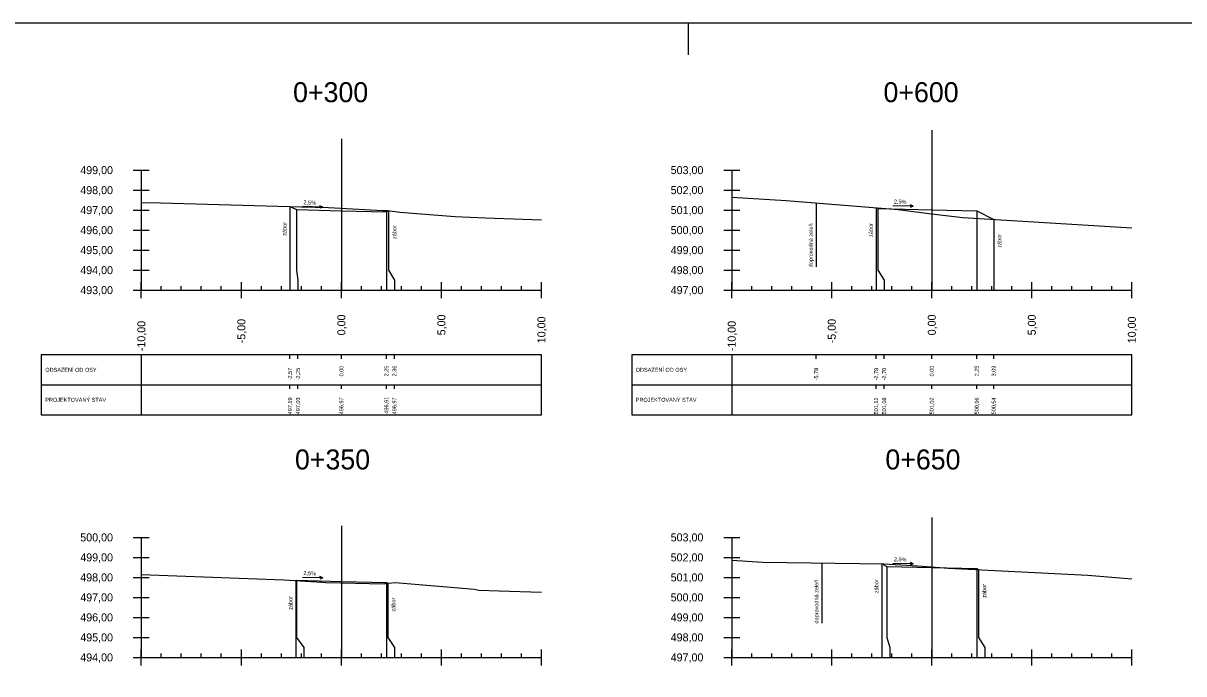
# Model space of a CAD drawing. Extents: x -631407 to -631215, y -1089700 to -1088598.
# Drawn here: x -631374.6 to -631316.6, y -1089327.7 to -1089295.2 of the extents above; entities that cross this region are included whole.
import ezdxf

# ---------------------------------------------------------------- set-up
doc = ezdxf.new("R2010")
doc.units = 0
for name, color, linetype in [('08_LEGENDA_HV', 7, 'Continuous'), ('59', 7, 'Continuous'), ('DTM-Breaklines', 7, 'Continuous'), ('NIVELETA_VYSKY', 7, 'Continuous'), ('REZ_BODY', 7, 'Continuous'), ('REZ_ODSTUPY', 7, 'Continuous'), ('REZ_POPIS', 7, 'Continuous'), ('REZ_RAMY', 7, 'Continuous'), ('REZ_STANICENI', 7, 'Continuous'), ('REZ_SVISLE', 7, 'Continuous'), ('REZ_TENKA', 7, 'Continuous'), ('REZ_TLUSTA', 7, 'Continuous'), ('TABULKA_POPIS', 7, 'Continuous'), ('TEREN', 7, 'Continuous'), ('zábor', 7, 'Continuous')]:
    doc.layers.add(name, color=color, linetype=linetype)

msp = doc.modelspace()

# ---------------------------------------------------------------- linework, layer by layer
at = {"layer": '08_LEGENDA_HV'}
msp.add_lwpolyline([(-631215.384, -1089413.965), (-631215.384, -1089295.165), (-631407.014, -1089295.165), (-631407.014, -1089413.965)], close=True, dxfattribs=at)
at = {"layer": '59'}
for p, q in [((-631369.144, -1089302.511), (-631368.344, -1089302.511)), ((-631368.744, -1089302.511), (-631368.744, -1089308.511)), ((-631339.63, -1089302.511), (-631338.83, -1089302.511)), ((-631339.23, -1089302.511), (-631339.23, -1089308.511)), ((-631369.144, -1089303.511), (-631368.344, -1089303.511)), ((-631339.63, -1089303.511), (-631338.83, -1089303.511)), ((-631369.144, -1089304.511), (-631368.344, -1089304.511)), ((-631339.63, -1089304.511), (-631338.83, -1089304.511)), ((-631369.144, -1089305.511), (-631368.344, -1089305.511)), ((-631339.63, -1089305.511), (-631338.83, -1089305.511)), ((-631369.144, -1089306.511), (-631368.344, -1089306.511)), ((-631339.63, -1089306.511), (-631338.83, -1089306.511)), ((-631369.144, -1089307.511), (-631368.344, -1089307.511)), ((-631339.63, -1089307.511), (-631338.83, -1089307.511)), ((-631369.144, -1089308.511), (-631368.344, -1089308.511)), ((-631339.63, -1089308.511), (-631338.83, -1089308.511)), ((-631369.144, -1089320.873), (-631368.344, -1089320.873)), ((-631368.744, -1089320.873), (-631368.744, -1089326.873)), ((-631339.63, -1089320.873), (-631338.83, -1089320.873)), ((-631339.23, -1089320.873), (-631339.23, -1089326.873)), ((-631369.144, -1089321.873), (-631368.344, -1089321.873)), ((-631339.63, -1089321.873), (-631338.83, -1089321.873)), ((-631369.144, -1089322.873), (-631368.344, -1089322.873)), ((-631339.63, -1089322.873), (-631338.83, -1089322.873)), ((-631369.144, -1089323.873), (-631368.344, -1089323.873)), ((-631339.63, -1089323.873), (-631338.83, -1089323.873)), ((-631369.144, -1089324.873), (-631368.344, -1089324.873)), ((-631339.63, -1089324.873), (-631338.83, -1089324.873)), ((-631369.144, -1089325.873), (-631368.344, -1089325.873)), ((-631339.63, -1089325.873), (-631338.83, -1089325.873)), ((-631369.144, -1089326.873), (-631368.344, -1089326.873)), ((-631339.63, -1089326.873), (-631338.83, -1089326.873))]:
    msp.add_line(p, q, dxfattribs=at)
at = {"layer": 'DTM-Breaklines'}
msp.add_line((-631341.384, -1089296.745), (-631341.384, -1089295.165), dxfattribs=at)
at = {"layer": 'REZ_RAMY'}
for p, q in [((-631373.744, -1089311.745), (-631373.744, -1089314.745)), ((-631368.744, -1089311.745), (-631368.744, -1089314.745)), ((-631361.313, -1089311.945), (-631361.313, -1089311.745)), ((-631360.913, -1089311.945), (-631360.913, -1089311.745)), ((-631358.744, -1089311.945), (-631358.744, -1089311.745)), ((-631356.494, -1089311.945), (-631356.494, -1089311.745)), ((-631356.094, -1089311.945), (-631356.094, -1089311.745)), ((-631344.23, -1089311.745), (-631344.23, -1089314.745)), ((-631339.23, -1089311.745), (-631339.23, -1089314.745)), ((-631335.01, -1089311.945), (-631335.01, -1089311.745)), ((-631332.01, -1089311.945), (-631332.01, -1089311.745)), ((-631331.61, -1089311.945), (-631331.61, -1089311.745)), ((-631329.23, -1089311.945), (-631329.23, -1089311.745)), ((-631326.98, -1089311.945), (-631326.98, -1089311.745)), ((-631326.135, -1089311.945), (-631326.135, -1089311.745)), ((-631373.744, -1089313.245), (-631348.744, -1089313.245)), ((-631361.313, -1089313.445), (-631361.313, -1089313.245)), ((-631360.913, -1089313.445), (-631360.913, -1089313.245)), ((-631358.744, -1089313.445), (-631358.744, -1089313.245)), ((-631356.494, -1089313.445), (-631356.494, -1089313.245)), ((-631356.094, -1089313.445), (-631356.094, -1089313.245)), ((-631344.23, -1089313.245), (-631319.23, -1089313.245)), ((-631332.01, -1089313.445), (-631332.01, -1089313.245)), ((-631331.61, -1089313.445), (-631331.61, -1089313.245)), ((-631329.23, -1089313.445), (-631329.23, -1089313.245)), ((-631326.98, -1089313.445), (-631326.98, -1089313.245)), ((-631326.135, -1089313.445), (-631326.135, -1089313.245))]:
    msp.add_line(p, q, dxfattribs=at)
for points in [[(-631373.744, -1089311.745), (-631373.744, -1089314.745), (-631348.744, -1089314.745), (-631348.744, -1089311.745)], [(-631344.23, -1089311.745), (-631344.23, -1089314.745), (-631319.23, -1089314.745), (-631319.23, -1089311.745)]]:
    msp.add_lwpolyline(points, close=True, dxfattribs=at)
at = {"layer": 'REZ_SVISLE'}
for points in [[(-631361.313, -1089304.326), (-631361.313, -1089307.511), (-631361.313, -1089308.011), (-631361.313, -1089308.511)], [(-631360.994, -1089304.486), (-631360.994, -1089307.511), (-631360.913, -1089308.011), (-631360.913, -1089308.511)], [(-631358.744, -1089304.542), (-631358.744, -1089307.511), (-631358.744, -1089308.011), (-631358.744, -1089308.511)], [(-631356.494, -1089304.598), (-631356.494, -1089307.511), (-631356.494, -1089308.011), (-631356.494, -1089308.511)], [(-631356.38, -1089304.541), (-631356.38, -1089307.511), (-631356.094, -1089308.011), (-631356.094, -1089308.511)], [(-631332.01, -1089304.39), (-631332.01, -1089307.511), (-631332.01, -1089308.011), (-631332.01, -1089308.511)], [(-631331.934, -1089304.428), (-631331.934, -1089307.511), (-631331.61, -1089308.011), (-631331.61, -1089308.511)], [(-631329.23, -1089304.496), (-631329.23, -1089307.511), (-631329.23, -1089308.011), (-631329.23, -1089308.511)], [(-631326.98, -1089304.552), (-631326.98, -1089307.511), (-631326.98, -1089308.011), (-631326.98, -1089308.511)], [(-631326.135, -1089304.974), (-631326.135, -1089307.511), (-631326.135, -1089308.011), (-631326.135, -1089308.511)], [(-631331.727, -1089322.198), (-631331.727, -1089325.873), (-631331.727, -1089326.373), (-631331.727, -1089326.873)], [(-631331.48, -1089322.322), (-631331.48, -1089325.873), (-631331.327, -1089326.373), (-631331.327, -1089326.873)], [(-631329.23, -1089322.378), (-631329.23, -1089325.873), (-631329.23, -1089326.373), (-631329.23, -1089326.873)], [(-631326.98, -1089322.435), (-631326.98, -1089325.873), (-631326.98, -1089326.373), (-631326.98, -1089326.873)], [(-631326.893, -1089322.478), (-631326.893, -1089325.873), (-631326.58, -1089326.373), (-631326.58, -1089326.873)], [(-631361.015, -1089323.029), (-631361.015, -1089325.873), (-631361.015, -1089326.373), (-631361.015, -1089326.873)], [(-631360.994, -1089323.018), (-631360.994, -1089325.873), (-631360.615, -1089326.373), (-631360.615, -1089326.873)], [(-631358.744, -1089323.074), (-631358.744, -1089325.873), (-631358.744, -1089326.373), (-631358.744, -1089326.873)], [(-631356.494, -1089323.131), (-631356.494, -1089325.873), (-631356.494, -1089326.373), (-631356.494, -1089326.873)], [(-631356.429, -1089323.163), (-631356.429, -1089325.873), (-631356.094, -1089326.373), (-631356.094, -1089326.873)]]:
    msp.add_lwpolyline(points, dxfattribs=at)
at = {"layer": 'REZ_TENKA'}
for p, q in [((-631367.744, -1089308.511), (-631367.744, -1089308.311)), ((-631366.744, -1089308.511), (-631366.744, -1089308.311)), ((-631365.744, -1089308.511), (-631365.744, -1089308.311)), ((-631364.744, -1089308.511), (-631364.744, -1089308.311)), ((-631362.744, -1089308.511), (-631362.744, -1089308.311)), ((-631361.744, -1089308.511), (-631361.744, -1089308.311)), ((-631360.744, -1089308.511), (-631360.744, -1089308.311)), ((-631359.744, -1089308.511), (-631359.744, -1089308.311)), ((-631357.744, -1089308.511), (-631357.744, -1089308.311)), ((-631356.744, -1089308.511), (-631356.744, -1089308.311)), ((-631355.744, -1089308.511), (-631355.744, -1089308.311)), ((-631354.744, -1089308.511), (-631354.744, -1089308.311)), ((-631352.744, -1089308.511), (-631352.744, -1089308.311)), ((-631351.744, -1089308.511), (-631351.744, -1089308.311)), ((-631350.744, -1089308.511), (-631350.744, -1089308.311)), ((-631349.744, -1089308.511), (-631349.744, -1089308.311)), ((-631338.23, -1089308.511), (-631338.23, -1089308.311)), ((-631337.23, -1089308.511), (-631337.23, -1089308.311)), ((-631336.23, -1089308.511), (-631336.23, -1089308.311)), ((-631335.23, -1089308.511), (-631335.23, -1089308.311)), ((-631333.23, -1089308.511), (-631333.23, -1089308.311)), ((-631332.23, -1089308.511), (-631332.23, -1089308.311)), ((-631331.23, -1089308.511), (-631331.23, -1089308.311)), ((-631330.23, -1089308.511), (-631330.23, -1089308.311)), ((-631328.23, -1089308.511), (-631328.23, -1089308.311)), ((-631327.23, -1089308.511), (-631327.23, -1089308.311)), ((-631326.23, -1089308.511), (-631326.23, -1089308.311)), ((-631325.23, -1089308.511), (-631325.23, -1089308.311)), ((-631323.23, -1089308.511), (-631323.23, -1089308.311)), ((-631322.23, -1089308.511), (-631322.23, -1089308.311)), ((-631321.23, -1089308.511), (-631321.23, -1089308.311)), ((-631320.23, -1089308.511), (-631320.23, -1089308.311)), ((-631367.744, -1089326.873), (-631367.744, -1089326.673)), ((-631366.744, -1089326.873), (-631366.744, -1089326.673)), ((-631365.744, -1089326.873), (-631365.744, -1089326.673)), ((-631364.744, -1089326.873), (-631364.744, -1089326.673)), ((-631362.744, -1089326.873), (-631362.744, -1089326.673)), ((-631361.744, -1089326.873), (-631361.744, -1089326.673)), ((-631360.744, -1089326.873), (-631360.744, -1089326.673)), ((-631359.744, -1089326.873), (-631359.744, -1089326.673)), ((-631357.744, -1089326.873), (-631357.744, -1089326.673)), ((-631356.744, -1089326.873), (-631356.744, -1089326.673)), ((-631355.744, -1089326.873), (-631355.744, -1089326.673)), ((-631354.744, -1089326.873), (-631354.744, -1089326.673)), ((-631352.744, -1089326.873), (-631352.744, -1089326.673)), ((-631351.744, -1089326.873), (-631351.744, -1089326.673)), ((-631350.744, -1089326.873), (-631350.744, -1089326.673)), ((-631349.744, -1089326.873), (-631349.744, -1089326.673)), ((-631338.23, -1089326.873), (-631338.23, -1089326.673)), ((-631337.23, -1089326.873), (-631337.23, -1089326.673)), ((-631336.23, -1089326.873), (-631336.23, -1089326.673)), ((-631335.23, -1089326.873), (-631335.23, -1089326.673)), ((-631333.23, -1089326.873), (-631333.23, -1089326.673)), ((-631332.23, -1089326.873), (-631332.23, -1089326.673)), ((-631331.23, -1089326.873), (-631331.23, -1089326.673)), ((-631330.23, -1089326.873), (-631330.23, -1089326.673)), ((-631328.23, -1089326.873), (-631328.23, -1089326.673)), ((-631327.23, -1089326.873), (-631327.23, -1089326.673)), ((-631326.23, -1089326.873), (-631326.23, -1089326.673)), ((-631325.23, -1089326.873), (-631325.23, -1089326.673)), ((-631323.23, -1089326.873), (-631323.23, -1089326.673)), ((-631322.23, -1089326.873), (-631322.23, -1089326.673)), ((-631321.23, -1089326.873), (-631321.23, -1089326.673)), ((-631320.23, -1089326.873), (-631320.23, -1089326.673))]:
    msp.add_line(p, q, dxfattribs=at)
at = {"layer": 'REZ_TLUSTA'}
for p, q in [((-631329.23, -1089300.511), (-631329.23, -1089308.511)), ((-631358.744, -1089300.938), (-631358.744, -1089308.511)), ((-631368.744, -1089308.911), (-631368.744, -1089308.111)), ((-631363.744, -1089308.911), (-631363.744, -1089308.111)), ((-631358.744, -1089308.911), (-631358.744, -1089308.111)), ((-631353.744, -1089308.911), (-631353.744, -1089308.111)), ((-631348.744, -1089308.911), (-631348.744, -1089308.111)), ((-631339.23, -1089308.911), (-631339.23, -1089308.111)), ((-631334.23, -1089308.911), (-631334.23, -1089308.111)), ((-631329.23, -1089308.911), (-631329.23, -1089308.111)), ((-631324.23, -1089308.911), (-631324.23, -1089308.111)), ((-631319.23, -1089308.911), (-631319.23, -1089308.111)), ((-631368.744, -1089308.511), (-631348.744, -1089308.511)), ((-631339.23, -1089308.511), (-631319.23, -1089308.511)), ((-631329.23, -1089319.873), (-631329.23, -1089326.873)), ((-631358.744, -1089320.29), (-631358.744, -1089326.873)), ((-631368.744, -1089327.273), (-631368.744, -1089326.473)), ((-631368.744, -1089326.873), (-631348.744, -1089326.873)), ((-631363.744, -1089327.273), (-631363.744, -1089326.473)), ((-631358.744, -1089327.273), (-631358.744, -1089326.473)), ((-631353.744, -1089327.273), (-631353.744, -1089326.473)), ((-631348.744, -1089327.273), (-631348.744, -1089326.473)), ((-631339.23, -1089327.273), (-631339.23, -1089326.473)), ((-631339.23, -1089326.873), (-631319.23, -1089326.873)), ((-631334.23, -1089327.273), (-631334.23, -1089326.473)), ((-631329.23, -1089327.273), (-631329.23, -1089326.473)), ((-631324.23, -1089327.273), (-631324.23, -1089326.473)), ((-631319.23, -1089327.273), (-631319.23, -1089326.473))]:
    msp.add_line(p, q, dxfattribs=at)
at = {"layer": 'TEREN'}
for points in [[(-631368.744, -1089304.121), (-631367.779, -1089304.148), (-631360.749, -1089304.341), (-631359.383, -1089304.374), (-631356.664, -1089304.53), (-631356.425, -1089304.535), (-631355.818, -1089304.613), (-631353.061, -1089304.828), (-631351.556, -1089304.904), (-631348.744, -1089304.997)], [(-631361.313, -1089304.326), (-631360.994, -1089304.486), (-631358.744, -1089304.542), (-631356.494, -1089304.598), (-631356.38, -1089304.541)], [(-631339.23, -1089303.859), (-631336.51, -1089304.031), (-631330.908, -1089304.478), (-631329.245, -1089304.696), (-631327.672, -1089304.88), (-631319.23, -1089305.397)], [(-631332.01, -1089304.39), (-631331.934, -1089304.428), (-631329.23, -1089304.496), (-631326.98, -1089304.552), (-631326.135, -1089304.974)], [(-631339.23, -1089322.003), (-631337.686, -1089322.11), (-631331.627, -1089322.2), (-631329.935, -1089322.298), (-631328.399, -1089322.403), (-631321.423, -1089322.753), (-631319.23, -1089322.937)], [(-631331.727, -1089322.198), (-631331.48, -1089322.322), (-631329.23, -1089322.378), (-631326.98, -1089322.435), (-631326.893, -1089322.478)], [(-631368.744, -1089322.73), (-631361.62, -1089322.989), (-631359.728, -1089323.113), (-631359.523, -1089323.129), (-631356.605, -1089323.196), (-631356.549, -1089323.176), (-631356.056, -1089323.123), (-631352.084, -1089323.464), (-631351.866, -1089323.507), (-631350.862, -1089323.547), (-631348.744, -1089323.603)], [(-631361.015, -1089323.029), (-631360.994, -1089323.018), (-631358.744, -1089323.074), (-631356.494, -1089323.131), (-631356.429, -1089323.163)]]:
    msp.add_lwpolyline(points, dxfattribs=at)
at = {"layer": 'zábor'}
for p, q in [((-631359.677, -1089304.362), (-631359.813, -1089304.298)), ((-631335.01, -1089304.151), (-631335.01, -1089307.348)), ((-631330.163, -1089304.316), (-631331.171, -1089304.291)), ((-631330.163, -1089304.316), (-631330.302, -1089304.374)), ((-631330.163, -1089304.316), (-631330.299, -1089304.252)), ((-631359.677, -1089304.362), (-631360.685, -1089304.337)), ((-631359.677, -1089304.362), (-631359.816, -1089304.42)), ((-631334.727, -1089322.154), (-631334.727, -1089325.157)), ((-631330.163, -1089322.199), (-631331.171, -1089322.174)), ((-631330.163, -1089322.199), (-631330.302, -1089322.256)), ((-631330.163, -1089322.199), (-631330.299, -1089322.134)), ((-631359.677, -1089322.895), (-631360.685, -1089322.87)), ((-631359.677, -1089322.895), (-631359.816, -1089322.953)), ((-631359.677, -1089322.895), (-631359.813, -1089322.83))]:
    msp.add_line(p, q, dxfattribs=at)

# ---------------------------------------------------------------- texts
at = {"layer": 'NIVELETA_VYSKY'}
for s, p in [('497,19', (-631361.213, -1089314.721)), ('497,03', (-631360.813, -1089314.721)), ('496,97', (-631358.644, -1089314.721)), ('496,91', (-631356.394, -1089314.688)), ('496,97', (-631355.994, -1089314.721)), ('501,12', (-631331.91, -1089314.721)), ('501,08', (-631331.51, -1089314.721)), ('501,02', (-631329.13, -1089314.721)), ('500,96', (-631326.88, -1089314.721)), ('500,54', (-631326.035, -1089314.721))]:
    msp.add_text(s, height=0.2, rotation=90, dxfattribs=at).set_placement(p)
at = {"layer": 'REZ_BODY'}
for s, p in [('-2,57', (-631361.213, -1089313.022)), ('-2,25', (-631360.813, -1089313.022)), ('0,00', (-631358.644, -1089312.824)), ('2,25', (-631356.394, -1089312.824)), ('2,36', (-631355.994, -1089312.824)), ('-5,78', (-631334.91, -1089313.022)), ('-2,78', (-631331.91, -1089313.022)), ('-2,70', (-631331.51, -1089313.022)), ('0,00', (-631329.13, -1089312.824)), ('2,25', (-631326.88, -1089312.824)), ('3,09', (-631326.035, -1089312.824))]:
    msp.add_text(s, height=0.2, rotation=90, dxfattribs=at).set_placement(p)
at = {"layer": 'REZ_ODSTUPY'}
for s, p in [('-10,00', (-631368.544, -1089311.563)), ('-5,00', (-631363.544, -1089311.167)), ('0,00', (-631358.544, -1089310.77)), ('5,00', (-631353.544, -1089310.77)), ('10,00', (-631348.544, -1089311.167)), ('-10,00', (-631339.03, -1089311.563)), ('-5,00', (-631334.03, -1089311.167)), ('0,00', (-631329.03, -1089310.77)), ('5,00', (-631324.03, -1089310.77)), ('10,00', (-631319.03, -1089311.167))]:
    msp.add_text(s, height=0.4, rotation=90, dxfattribs=at).set_placement(p)
at = {"layer": 'REZ_POPIS'}
for s, p in [('499,00', (-631371.796, -1089302.711)), ('503,00', (-631342.282, -1089302.711)), ('498,00', (-631371.796, -1089303.711)), ('502,00', (-631342.282, -1089303.711)), ('497,00', (-631371.796, -1089304.711)), ('501,00', (-631342.282, -1089304.711)), ('496,00', (-631371.796, -1089305.711)), ('500,00', (-631342.282, -1089305.711)), ('495,00', (-631371.796, -1089306.711)), ('499,00', (-631342.282, -1089306.711)), ('494,00', (-631371.796, -1089307.711)), ('498,00', (-631342.282, -1089307.711)), ('493,00', (-631371.796, -1089308.711)), ('497,00', (-631342.282, -1089308.711)), ('500,00', (-631371.796, -1089321.073)), ('503,00', (-631342.282, -1089321.073)), ('499,00', (-631371.796, -1089322.073)), ('502,00', (-631342.282, -1089322.073)), ('498,00', (-631371.796, -1089323.073)), ('501,00', (-631342.282, -1089323.073)), ('497,00', (-631371.796, -1089324.073)), ('500,00', (-631342.282, -1089324.073)), ('496,00', (-631371.796, -1089325.073)), ('499,00', (-631342.282, -1089325.073)), ('495,00', (-631371.796, -1089326.073)), ('498,00', (-631342.282, -1089326.073)), ('494,00', (-631371.796, -1089327.073)), ('497,00', (-631342.282, -1089327.073))]:
    msp.add_text(s, height=0.4, dxfattribs=at).set_placement(p)
at = {"layer": 'REZ_STANICENI'}
for s, p in [('0+300', (-631361.158, -1089299.115)), ('0+600', (-631331.644, -1089299.115)), ('0+350', (-631361.063, -1089317.476)), ('0+650', (-631331.549, -1089317.476))]:
    msp.add_text(s, height=1, dxfattribs=at).set_placement(p)
at = {"layer": 'TABULKA_POPIS'}
for s, p in [('ODSAZENÍ OD OSY', (-631373.544, -1089312.595)), ('ODSAZENÍ OD OSY', (-631344.03, -1089312.595)), ('PROJEKTOVANÝ STAV', (-631373.544, -1089314.095)), ('PROJEKTOVANÝ STAV', (-631344.03, -1089314.095))]:
    msp.add_text(s, height=0.2, dxfattribs=at).set_placement(p)
at = {"layer": 'zábor'}
for s, rotation, p in [('2,5%', 358.5679, (-631360.641, -1089304.225)), ('2,5%', 358.5679, (-631331.127, -1089304.179)), ('zábor', 90, (-631361.483, -1089305.789)), ('zábor', 90, (-631355.997, -1089305.956)), ('doprovodná zeleň', 90, (-631335.178, -1089307.373)), ('zábor', 90, (-631332.18, -1089305.853)), ('zábor', 90, (-631325.752, -1089306.389)), ('2,5%', 358.5679, (-631331.127, -1089322.062)), ('2,5%', 358.5679, (-631360.641, -1089322.758)), ('doprovodná zeleň', 90, (-631334.895, -1089325.181)), ('zábor', 90, (-631331.898, -1089323.662)), ('zábor', 90, (-631326.51, -1089323.893)), ('zábor', 90, (-631361.185, -1089324.492)), ('zábor', 90, (-631356.046, -1089324.578))]:
    msp.add_text(s, height=0.2, rotation=rotation, dxfattribs=at).set_placement(p)

doc.saveas('drawing.dxf')
